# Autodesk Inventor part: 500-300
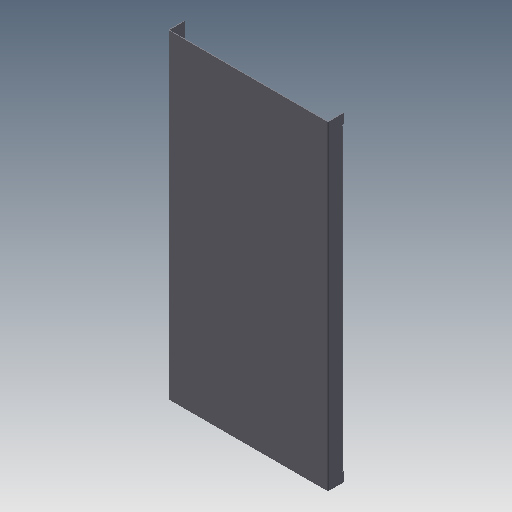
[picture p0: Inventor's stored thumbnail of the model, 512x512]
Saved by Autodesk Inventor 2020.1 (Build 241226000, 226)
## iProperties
Created: 2010-10
Part Number: 500-300
Material: St1203
Document SubType Name: Konstrukcje blachowe
Designer: F.Stasiak
Density: 7.85 g/cm^3
Sheet Metal Rule: Blacha stalowa 2.5 mm/Okrągły
Description: =Ściana prawa <WYSOKOŚĆ> x <SZEROKOŚĆ> pełna
Appearance: Metal-Stal
Company: Fabian Stasiak CAD Consulting
Manager: www.cadconsulting.pl
SZEROKOŚĆ: 500
WYSOKOŚĆ: 1000
Author: F.Stasiak
Subject: Zbiór ćwiczeń. Autodesk Inventor 2020. Kurs podstawowy
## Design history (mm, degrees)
node "Powierzchnia1"
  sketch "Szkic1"
    geometry: L1 (-250, 1000)-(250, 1000); L2 (250, 1000)-(250, 0); L3 (250, 0)-(-250, 0); L4 (-250, 0)-(-250, 1000); 2 further points
    constraints: 8 end point, 2 parallel, 1 coincident, 1 horizontal, 1 midpoint, 1 perpendicular
    dimensions: "d0" = 500 distance of L2.end L3.end; "d1" = 1000 distance of L1.end L2.end
node "Kołnierz1"
node "Kołnierz2"
feature "Zawinięcie obrzeża1" dims "d25" = 2.5 (= SzerokośćGięciaPodcięcia), "d26" = 1.25 (= GłębokośćGięciaPodcięcia), "d27" = 5 (= MinimalnaPozostałość), "d28" = 2.5 (= PromieńGięcia), "d29" = 10 (= 4 x Grubość), "d30" = 1.25 (= 0.5 x Grubość), "d31" = 0.625 (= 0.5 x d30), "d54" = 2.5 (= Grubość), "OdstępPołączenia" = 0.01
sketch "Szkic6"
  geometry: L1 (-45, 1000)-(-45, 0) reference; L2 (0, 0)-(-45, 0) reference; L3 (0, 0)-(0, 1000) reference; L4 (0, 1000)-(-45, 1000) reference; L5 (-22.5, 0)-(-22.5, 1000); 3 further points
  constraints: 2 end point, 2 midpoint, 2 point on line
  dimensions: "d45" = 130 distance from line of L2 point (-22.5, 130); "d46" = 150 distance from line of L4 point (-22.5, 850)
hole "Hole1" sketch "Szkic6" at (-22.5, 130), (-22.5, 850) diameter "d47" = 12; stored, may be unused: countersink angle "d51" = 90 deg, drill point angle "d53" = 118 deg; dims "d48" = 6, "d49" = 4, "d50" = 2, "d52" = 2.5 (= Grubość)
node "Bryła1"
feature "Płyta1" dims "d54" = 2.5 (= Grubość)
sketch "Szkic2"
  geometry: L1 (0, -50)-(1000, -50); L2 (1000, -50)-(1000, 0); 1 other entity
  constraints: 4 end point, 4 other
feature "Płyta2" dims "d3" = 2.5 (= SzerokośćGięciaPodcięcia), "d4" = 1.25 (= GłębokośćGięciaPodcięcia), "d5" = 5 (= MinimalnaPozostałość), "d6" = 2.5 (= PromieńGięcia), "d7" = 50, "d8" = 90 deg, "d9" = 2.5 (= PromieńGięcia), "d10" = 10 (= RozmiarPodcięciaNarożnika), "d11" = 2.5 (= Wielk_odstępu), "d12" = 2.5 (= Rozmiar_promienia_Jacobiego), "d54" = 2.5 (= Grubość), "OdstępPołączenia" = 0.01
feature "Gięcie1" dims "d3" = 2.5 (= SzerokośćGięciaPodcięcia), "d4" = 1.25 (= GłębokośćGięciaPodcięcia), "d5" = 5 (= MinimalnaPozostałość), "d6" = 2.5 (= PromieńGięcia), "d7" = 50, "d8" = 90 deg, "d9" = 2.5 (= PromieńGięcia), "d54" = 2.5 (= Grubość), "OdstępPołączenia" = 0.01
feature "Narożnik1" dims "d7" = 50, "d8" = 90 deg, "d10" = 10 (= RozmiarPodcięciaNarożnika), "d11" = 2.5 (= Wielk_odstępu), "d12" = 2.5 (= Rozmiar_promienia_Jacobiego)
sketch "Szkic3"
  geometry: L1 (0, 968)-(0, 32); L2 (0, 32)-(20, 32); L3 (20, 32)-(20, 968); L4 (20, 968)-(0, 968)
  constraints: 8 end point
feature "Płyta3" dims "d13" = 2.5 (= SzerokośćGięciaPodcięcia), "d14" = 1.25 (= GłębokośćGięciaPodcięcia), "d15" = 5 (= MinimalnaPozostałość), "d16" = 2.5 (= PromieńGięcia), "d17" = 32, "d18" = 32, "d19" = 20, "d20" = 90 deg, "d21" = 2.5 (= PromieńGięcia), "d22" = 10 (= RozmiarPodcięciaNarożnika), "d23" = 2.5 (= Wielk_odstępu), "d24" = 2.5 (= Rozmiar_promienia_Jacobiego), "d54" = 2.5 (= Grubość), "OdstępPołączenia" = 0.01
feature "Gięcie2" dims "d13" = 2.5 (= SzerokośćGięciaPodcięcia), "d14" = 1.25 (= GłębokośćGięciaPodcięcia), "d15" = 5 (= MinimalnaPozostałość), "d16" = 2.5 (= PromieńGięcia), "d19" = 20, "d20" = 90 deg, "d21" = 2.5 (= PromieńGięcia), "d54" = 2.5 (= Grubość), "OdstępPołączenia" = 0.01
feature "Narożnik2" dims "d19" = 20, "d20" = 90 deg, "d22" = 10 (= RozmiarPodcięciaNarożnika), "d23" = 2.5 (= Wielk_odstępu), "d24" = 2.5 (= Rozmiar_promienia_Jacobiego)
node "Pętla rzutowana1"
sketch "Szkic4"
  geometry: L1 (0, -2.5)-(0, 0); L2 (0, 1.25)-(-6.875, 1.25); L3 (-6.875, 1.25)-(-6.875, 3.75); L4 (-6.875, 3.75)-(0, 3.75); A1 r 0.625 centre (0, 0.625) between (0, 0) and (0, 1.25); A2 r 3.125 centre (0, 0.625) between (0, -2.5) and (0, 3.75)
  constraints: 8 end point, 4 point on circle
other parameters: "Grubość" = 2.5 (derived), "WspółczynnikK" = 4.4, "PromieńGięcia" = 2.5 (= Grubość), "SzerokośćGięciaPodcięcia" = 2.5 (= Grubość), "GłębokośćGięciaPodcięcia" = 1.25 (= 0.5 x Grubość), "MinimalnaPozostałość" = 5 (= 2 x Grubość), "PromieńPrzejścia" = 2.5 (= PromieńGięcia), "Rozmiar_promienia_Jacobiego" = 2.5 (= PromieńGięcia), "Wielk_odstępu" = 2.5 (= Grubość), "d2" = 2.5 (= PromieńGięcia)
